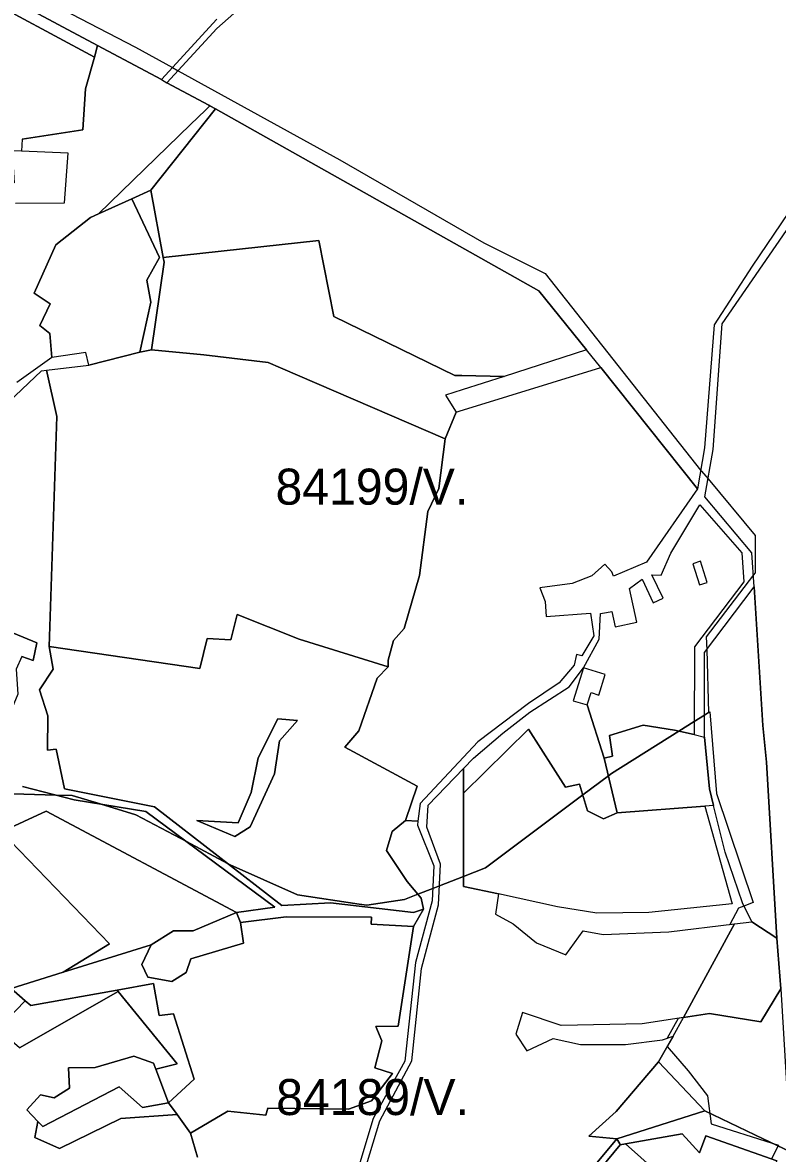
# Model space of a CAD drawing. Extents: x -477304 to -465429, y -1159113 to -1149210.
# Drawn here: x -474880.8 to -474566.3, y -1157226 to -1156755 of the extents above; entities that cross this region are included whole.
import ezdxf

# ---------------------------------------------------------------- set-up
doc = ezdxf.new("R2010")
doc.units = 0
for name, color, linetype in [('BPEJ_s', 7, 'Continuous'), ('PUPFL_s', 7, 'Continuous'), ('sad_s', 7, 'Continuous'), ('trav_porost_s', 7, 'Continuous'), ('zahrada_s', 7, 'Continuous')]:
    doc.layers.add(name, color=color, linetype=linetype)

msp = doc.modelspace()

# ---------------------------------------------------------------- linework, layer by layer
at = {"layer": 'BPEJ_s'}
for points in [[(-474910.48, -1156725.34), (-474833.78, -1156765.24), (-474818.36, -1156773.73), (-474815.98, -1156775.04), (-474748.53, -1156812.18), (-474688.56, -1156846.68), (-474662.99, -1156859.58), (-474598.28, -1156941.38), (-474597.89, -1156941.87), (-474595.22, -1156945.08), (-474575.63, -1156968.65), (-474575.63, -1156984.14), (-474576.28, -1156985), (-474595.92, -1157010.92), (-474595.77, -1157016.21), (-474595.07, -1157042.42), (-474596.66, -1157043.42), (-474600.95, -1157046.11), (-474607.31, -1157050.1), (-474635.4, -1157067.73), (-474636.7, -1157068.7), (-474647.39, -1157076.7), (-474666.82, -1157091.23), (-474687.96, -1157107.04), (-474697.12, -1157110.64), (-474707.06, -1157114.55), (-474709.92, -1157115.67), (-474716.07, -1157118.09), (-474721.66, -1157120.28), (-474737.3, -1157122.69), (-474740.55, -1157122.19), (-474766.19, -1157118.28), (-474794.27, -1157105.84), (-474795.36, -1157105.26), (-474812.52, -1157096.15), (-474833.58, -1157084.98), (-474848.45, -1157080.47), (-474860.06, -1157076.96), (-474866.9, -1157076.77), (-474898.2, -1157075.9)], [(-474910.48, -1156725.34), (-474833.78, -1156765.24), (-474818.36, -1156773.73), (-474815.98, -1156775.04), (-474748.53, -1156812.18), (-474688.56, -1156846.68), (-474662.99, -1156859.58), (-474598.28, -1156941.38), (-474597.89, -1156941.87), (-474595.22, -1156945.08), (-474575.63, -1156968.65), (-474575.63, -1156984.14), (-474576.28, -1156985), (-474595.92, -1157010.92), (-474595.77, -1157016.21), (-474595.07, -1157042.42), (-474594.48, -1157042.05), (-474591.67, -1157076.15), (-474576.43, -1157121.49), (-474580.25, -1157123.01), (-474582.45, -1157123.89)], [(-474898.2, -1157075.9), (-474866.9, -1157076.77), (-474860.06, -1157076.96), (-474848.45, -1157080.47), (-474833.58, -1157084.98), (-474812.52, -1157096.15), (-474795.36, -1157105.26), (-474794.27, -1157105.84), (-474766.19, -1157118.28), (-474740.55, -1157122.19), (-474737.3, -1157122.69), (-474721.66, -1157120.28), (-474716.07, -1157118.09), (-474709.92, -1157115.67), (-474707.06, -1157114.55), (-474697.12, -1157110.64), (-474687.96, -1157107.04), (-474666.82, -1157091.23), (-474647.39, -1157076.7), (-474636.7, -1157068.7), (-474635.4, -1157067.73), (-474607.31, -1157050.1), (-474600.95, -1157046.11), (-474596.66, -1157043.42), (-474595.07, -1157042.42), (-474594.48, -1157042.05), (-474591.67, -1157076.15), (-474576.43, -1157121.49), (-474580.25, -1157123.01), (-474582.45, -1157123.89), (-474586.17, -1157130.66), (-474584.16, -1157130.41), (-474605.49, -1157169.45), (-474607.69, -1157169.78), (-474612.24, -1157178.05), (-474609.75, -1157177.25), (-474612.17, -1157181.44), (-474603.51, -1157191.69), (-474595.49, -1157202.12), (-474593.88, -1157213.76), (-474568.54, -1157221.72), (-474565.8, -1157222.58)], [(-474582.45, -1157123.89), (-474586.17, -1157130.66), (-474584.16, -1157130.41), (-474605.49, -1157169.45), (-474607.69, -1157169.78), (-474612.24, -1157178.05), (-474609.75, -1157177.25), (-474612.17, -1157181.44), (-474603.51, -1157191.69), (-474595.49, -1157202.12), (-474593.88, -1157213.76), (-474568.54, -1157221.72), (-474565.8, -1157222.58), (-474565.99, -1157222.94), (-474568.82, -1157228.32)], [(-474565.99, -1157222.94), (-474568.82, -1157228.32)]]:
    msp.add_lwpolyline(points, dxfattribs=at)
at = {"layer": 'PUPFL_s'}
for points in [[(-475050.35, -1156724.49), (-474996.9, -1156722.67), (-474961.41, -1156717.1), (-474960.45, -1156713.18), (-474943.01, -1156716.72), (-474943.36, -1156718.88), (-474915.25, -1156729.45), (-474849.5, -1156764.55), (-474850.84, -1156769.41), (-474917.11, -1156733.69), (-474943.69, -1156724.45), (-474962.53, -1156722.23), (-474995.47, -1156727.45), (-475052.09, -1156729.69)], [(-474802.7, -1156789.7), (-474800.43, -1156790.91), (-474827.36, -1156824.84), (-474835.24, -1156828.37), (-474849.11, -1156834.6), (-474810.78, -1156797.51), (-474804.6, -1156791.54)], [(-474822.17, -1156852.91), (-474827.36, -1156824.84), (-474800.43, -1156790.91), (-474696.54, -1156849.32), (-474665.65, -1156866.69), (-474645.81, -1156891.37), (-474680.15, -1156902.39), (-474697.83, -1156902.04), (-474700.63, -1156901.99), (-474751.16, -1156877.41), (-474757.34, -1156845.8)], [(-474572.44, -1157047.84), (-474570.88, -1157063.12), (-474566.57, -1157136.41), (-474577.01, -1157129.52), (-474580.91, -1157121.68), (-474588.03, -1157100.57), (-474592.92, -1157081.06), (-474594.63, -1157074.21), (-474596.67, -1157052.59), (-474596.64, -1157017.35), (-474575.93, -1156990.04)], [(-474899.13, -1157070.68), (-474916.01, -1157075.74), (-474938.95, -1157077.02), (-474954.17, -1157078.25), (-474987.5, -1157074.55), (-475015.54, -1157060.67), (-474955.56, -1157054.06), (-474895.66, -1157047.4), (-474884.52, -1157009.38), (-474874.79, -1157013.4), (-474876.41, -1157020.73), (-474881.13, -1157019.11), (-474883.41, -1157024.26), (-474882.74, -1157034.73), (-474885.83, -1157042.11), (-474889.45, -1157047.94), (-474898.18, -1157051.61), (-474901.76, -1157056.2), (-474896.84, -1157066.23)], [(-474870.93, -1157083.43), (-474791.58, -1157125.7), (-474809.64, -1157133.34), (-474817.86, -1157133.29), (-474827.16, -1157139.1), (-474863.81, -1157150.57), (-474844.56, -1157138.8), (-474889.52, -1157092.08)], [(-474885.46, -1157157.34), (-474863.81, -1157150.57), (-474827.16, -1157139.1), (-474831.12, -1157147.34), (-474828.52, -1157152.62), (-474818.58, -1157154.46), (-474812.65, -1157150.67), (-474810.67, -1157145.03), (-474788.67, -1157138.53), (-474790.04, -1157129.85), (-474770.97, -1157127.53), (-474735.38, -1157127.68), (-474735.49, -1157130.57), (-474717.93, -1157131.51), (-474724.3, -1157173.08), (-474733.65, -1157173.24), (-474731.13, -1157179.21), (-474733.98, -1157190.4), (-474726.72, -1157192.71), (-474735.37, -1157204.16), (-474744.95, -1157207.61), (-474778.63, -1157207.26), (-474779.36, -1157210.08), (-474795.27, -1157208.41), (-474810.86, -1157217.55), (-474816.41, -1157209.79), (-474819.97, -1157204.97), (-474809.26, -1157195.07), (-474817.86, -1157167.91), (-474823.93, -1157168.6), (-474826.26, -1157155.32), (-474841.42, -1157158.09), (-474877.38, -1157164.49), (-474879.64, -1157162.52)], [(-474790.04, -1157129.85), (-474788.67, -1157138.53), (-474810.67, -1157145.03), (-474812.65, -1157150.67), (-474818.58, -1157154.46), (-474828.52, -1157152.62), (-474831.12, -1157147.34), (-474827.16, -1157139.1), (-474817.86, -1157133.29), (-474809.64, -1157133.34), (-474791.58, -1157125.7)], [(-474584.16, -1157130.41), (-474577.01, -1157129.52), (-474566.57, -1157136.41), (-474564.87, -1157157.45), (-474573.26, -1157171.3), (-474594.56, -1157167.78), (-474605.49, -1157169.45)], [(-474826.26, -1157155.32), (-474823.93, -1157168.6), (-474817.86, -1157167.91), (-474809.26, -1157195.07), (-474819.97, -1157204.97), (-474825.25, -1157190.92), (-474816.38, -1157188.78), (-474840.97, -1157158.64), (-474841.42, -1157158.09)], [(-474560.83, -1157225.42), (-474572.19, -1157219.97), (-474596.58, -1157208.26), (-474615.85, -1157187.83), (-474609.75, -1157177.25), (-474605.49, -1157169.45), (-474594.56, -1157167.78), (-474573.26, -1157171.3), (-474564.87, -1157157.45), (-474561, -1157222.59)], [(-474841.42, -1157158.09), (-474840.97, -1157158.64), (-474882.08, -1157182.04), (-474891.25, -1157174.3), (-474879.64, -1157162.52), (-474877.38, -1157164.49)], [(-474840.56, -1157198.28), (-474872.33, -1157214.78), (-474874.37, -1157212.68), (-474878.97, -1157207.94), (-474873.24, -1157201.61), (-474867.67, -1157202.84), (-474861.27, -1157198.93), (-474861.69, -1157190.35), (-474850.56, -1157190.29), (-474834.35, -1157185.49), (-474826.18, -1157188.45), (-474825.25, -1157190.92), (-474819.97, -1157204.97), (-474830.81, -1157206.94)], [(-474596.58, -1157208.26), (-474633.21, -1157219.92), (-474644.9, -1157218.82), (-474633.44, -1157208.55), (-474615.85, -1157187.83)], [(-474819.97, -1157204.97), (-474816.41, -1157209.79), (-474839.83, -1157211.52), (-474865.42, -1157223.93), (-474875.71, -1157219.47), (-474874.37, -1157212.68), (-474872.33, -1157214.78), (-474840.56, -1157198.28), (-474830.81, -1157206.94)], [(-474585.32, -1157258.29), (-474592.58, -1157249.28), (-474610.48, -1157239.07), (-474629.62, -1157222.07), (-474606.02, -1157217.85), (-474598.76, -1157225.82), (-474596.12, -1157218.7), (-474566.5, -1157229.14), (-474577.17, -1157250.19)]]:
    msp.add_lwpolyline(points, close=True, dxfattribs=at)
for points in [[(-474799.8, -1156753.54), (-474822.94, -1156778.71), (-474849.5, -1156764.55), (-474915.25, -1156729.45)], [(-474561.74, -1156834.07), (-474576.86, -1156856.4), (-474592.59, -1156880.96), (-474596.64, -1156932.07), (-474599.66, -1156949.17), (-474639.91, -1156898.7), (-474645.81, -1156891.37), (-474665.65, -1156866.69), (-474696.54, -1156849.32), (-474800.43, -1156790.91), (-474802.7, -1156789.7), (-474803.2, -1156789.43), (-474820.67, -1156780.13), (-474799.84, -1156757.52), (-474773.73, -1156734.29)], [(-474564.87, -1157157.45), (-474566.57, -1157136.41), (-474570.88, -1157063.12), (-474572.44, -1157047.84), (-474575.93, -1156990.04), (-474576.91, -1156975.84), (-474596.49, -1156952.51), (-474593.11, -1156932.76), (-474589.27, -1156880.49), (-474559.69, -1156837.53)], [(-474566.5, -1157229.14), (-474596.12, -1157218.7), (-474598.76, -1157225.82), (-474606.02, -1157217.85), (-474629.62, -1157222.07), (-474631.77, -1157222.45), (-474632, -1157222.05), (-474633.21, -1157219.92), (-474596.58, -1157208.26), (-474572.19, -1157219.97), (-474560.83, -1157225.42), (-474520.06, -1157230.66)], [(-474641.34, -1157229.79), (-474633.21, -1157219.92), (-474632, -1157222.05), (-474631.77, -1157222.45), (-474654.35, -1157249.7)]]:
    msp.add_lwpolyline(points, dxfattribs=at)
at = {"layer": 'sad_s'}
for points in [[(-474622.63, -1156986.84), (-474618.06, -1156996.69), (-474613.96, -1156994.71), (-474618.65, -1156984.99), (-474614.68, -1156985.24), (-474610.7, -1156975.97), (-474598.57, -1156955.93), (-474581.13, -1156975.81), (-474580.25, -1156988.01), (-474600.88, -1157015.06), (-474600.97, -1157051.58), (-474609.13, -1157049.68), (-474622.22, -1157047.6), (-474636.27, -1157051.92), (-474634.94, -1157060.53), (-474638.42, -1157061.35), (-474645.54, -1157039.25), (-474643.96, -1157034.09), (-474640.66, -1157035.1), (-474638.02, -1157026.51), (-474647.14, -1157023.71), (-474640.58, -1157011.8), (-474639.94, -1157001.19), (-474637.52, -1157000.73), (-474635.26, -1157000.24), (-474633.94, -1157006.65), (-474624.91, -1157004.71), (-474627.92, -1156990.68)], [(-474598.8, -1156989.18), (-474595.58, -1156988.19), (-474598.28, -1156979.4), (-474601.5, -1156980.39)]]:
    msp.add_lwpolyline(points, close=True, dxfattribs=at)
at = {"layer": 'trav_porost_s'}
for points in [[(-474917.11, -1156733.69), (-474850.84, -1156769.41), (-474854.5, -1156782.61), (-474855.65, -1156799.69), (-474880.95, -1156803.52), (-474881.2, -1156808.54), (-474885.06, -1156808.36), (-474884.2, -1156821.7), (-474890.84, -1156821.58), (-474898.09, -1156823.96), (-474910, -1156822.29), (-474919.21, -1156823.96), (-474937.87, -1156822.95), (-474956.33, -1156815.29), (-474954.66, -1156799.69), (-474957.43, -1156799.06), (-474956.8, -1156783.48), (-474969.9, -1156783.16), (-474979.46, -1156770.59), (-475008.23, -1156766.57), (-475008.3, -1156757.48), (-475065.69, -1156758.54), (-475057.96, -1156746.55)], [(-474880.95, -1156803.52), (-474855.65, -1156799.69), (-474854.5, -1156782.61), (-474850.84, -1156769.41), (-474849.5, -1156764.55), (-474822.94, -1156778.71), (-474820.67, -1156780.13), (-474803.2, -1156789.43), (-474802.7, -1156789.7), (-474804.6, -1156791.54), (-474810.78, -1156797.51), (-474849.11, -1156834.6), (-474852.51, -1156836.13), (-474866.92, -1156847.55), (-474875.91, -1156867.71), (-474869.28, -1156872.11), (-474873.55, -1156881.11), (-474869.47, -1156884.55), (-474868.62, -1156894.47), (-474883.15, -1156904.87)], [(-474883.65, -1156830.25), (-474863.32, -1156830.02), (-474861.74, -1156809.45), (-474881.2, -1156808.54)], [(-474900.21, -1156925.95), (-474872.85, -1156900.05), (-474870.76, -1156899.79), (-474866.46, -1156919.14), (-474869.63, -1157014.82), (-474867.97, -1157024.34), (-474873.65, -1157032.91), (-474870.2, -1157043.77), (-474870.4, -1157058.12), (-474866.82, -1157057.71), (-474863.3, -1157074.24), (-474825.8, -1157081.72), (-474772.76, -1157122.74), (-474752.48, -1157121.69), (-474717.92, -1157125.65), (-474713.79, -1157124.35), (-474717.93, -1157131.51), (-474735.49, -1157130.57), (-474735.38, -1157127.68), (-474770.97, -1157127.53), (-474790.04, -1157129.85), (-474791.58, -1157125.7), (-474775.67, -1157123.44), (-474829.48, -1157083.6), (-474859.22, -1157078.7), (-474880.78, -1157073.27)], [(-474881.13, -1157019.11), (-474876.41, -1157020.73), (-474874.79, -1157013.4), (-474884.52, -1157009.38)], [(-474744.45, -1157253.74), (-474731.98, -1157212.54), (-474718.64, -1157187.47), (-474714.57, -1157149.07), (-474707.46, -1157122.5), (-474706.6, -1157105.5), (-474712.3, -1157090.12), (-474711.77, -1157081.02), (-474697.14, -1157065.72), (-474697.14, -1157075.96), (-474697.12, -1157114.79), (-474682.5, -1157117.96), (-474683.74, -1157126.33), (-474676.33, -1157130.37), (-474666.69, -1157138.27), (-474654.51, -1157143.3), (-474647.29, -1157133.3), (-474638.93, -1157134.9), (-474611.52, -1157133.81), (-474584.16, -1157130.41), (-474605.49, -1157169.45), (-474622.58, -1157172.06), (-474656.34, -1157172.79), (-474672.48, -1157167.35), (-474675.21, -1157176.43), (-474670.72, -1157183.31), (-474659.7, -1157178.19), (-474648.37, -1157180.72), (-474629.54, -1157180.69), (-474614.24, -1157178.7), (-474609.75, -1157177.25), (-474615.85, -1157187.83), (-474633.44, -1157208.55), (-474644.9, -1157218.82), (-474633.21, -1157219.92), (-474641.34, -1157229.79)], [(-474880.78, -1157073.27), (-474859.22, -1157078.7), (-474829.48, -1157083.6), (-474775.67, -1157123.44), (-474791.58, -1157125.7), (-474870.93, -1157083.43), (-474889.52, -1157092.08), (-474844.56, -1157138.8), (-474863.81, -1157150.57), (-474885.46, -1157157.34), (-474879.64, -1157162.52), (-474891.25, -1157174.3)], [(-474807.85, -1157227.61), (-474810.86, -1157217.55), (-474795.27, -1157208.41), (-474779.36, -1157210.08), (-474778.63, -1157207.26), (-474744.95, -1157207.61), (-474735.37, -1157204.16), (-474726.72, -1157192.71), (-474733.98, -1157190.4), (-474731.13, -1157179.21), (-474733.65, -1157173.24), (-474724.3, -1157173.08), (-474717.93, -1157131.51), (-474713.79, -1157124.35), (-474714.76, -1157119.68), (-474720.48, -1157112.75), (-474729.18, -1157099.93), (-474726.76, -1157091.95), (-474721.28, -1157087.35), (-474716.08, -1157087.65), (-474716.28, -1157089.36), (-474709.5, -1157106.25), (-474710.15, -1157120.87), (-474717.1, -1157146.51), (-474721.55, -1157187.56), (-474734.77, -1157211.44), (-474746.21, -1157249.78)], [(-474882.08, -1157182.04), (-474840.97, -1157158.64), (-474816.38, -1157188.78), (-474825.25, -1157190.92), (-474826.18, -1157188.45), (-474834.35, -1157185.49), (-474850.56, -1157190.29), (-474861.69, -1157190.35), (-474861.27, -1157198.93), (-474867.67, -1157202.84), (-474873.24, -1157201.61), (-474878.97, -1157207.94), (-474874.37, -1157212.68), (-474875.71, -1157219.47), (-474865.42, -1157223.93), (-474839.83, -1157211.52), (-474816.41, -1157209.79), (-474810.86, -1157217.55), (-474807.85, -1157227.61)]]:
    msp.add_lwpolyline(points, dxfattribs=at)
for points in [[(-474835.24, -1156828.37), (-474827.36, -1156824.84), (-474822.17, -1156852.91), (-474821.83, -1156854.75), (-474826.99, -1156891.24), (-474831.94, -1156892.27), (-474827.29, -1156871.48), (-474828.98, -1156862.34), (-474823.7, -1156852.78)], [(-474849.11, -1156834.6), (-474835.24, -1156828.37), (-474823.7, -1156852.78), (-474828.98, -1156862.34), (-474827.29, -1156871.48), (-474831.94, -1156892.27), (-474853.14, -1156897.63), (-474854.42, -1156892.4), (-474868.62, -1156894.47), (-474869.47, -1156884.55), (-474873.55, -1156881.11), (-474869.28, -1156872.11), (-474875.91, -1156867.71), (-474866.92, -1156847.55), (-474852.51, -1156836.13)], [(-474751.16, -1156877.41), (-474700.63, -1156901.99), (-474697.83, -1156902.04), (-474680.15, -1156902.39), (-474697.57, -1156907.98), (-474704.57, -1156910.22), (-474700.19, -1156917.31), (-474704.76, -1156928.45), (-474773.25, -1156898.86), (-474778.46, -1156896.61), (-474805.27, -1156893.34), (-474826.99, -1156891.24), (-474821.83, -1156854.75), (-474822.17, -1156852.91), (-474757.34, -1156845.8)], [(-474773.25, -1156898.86), (-474704.76, -1156928.45), (-474707.42, -1156949.11), (-474711.92, -1156958.64), (-474715.41, -1156985.25), (-474721.76, -1157007.37), (-474726.25, -1157012.44), (-474728.5, -1157020.58), (-474728.44, -1157023.36), (-474765.56, -1157011.88), (-474791.3, -1157001.58), (-474794.01, -1157012.04), (-474803.83, -1157011.5), (-474806.92, -1157024.07), (-474869.63, -1157014.82), (-474866.46, -1156919.14), (-474870.76, -1156899.79), (-474853.14, -1156897.63), (-474831.94, -1156892.27), (-474826.99, -1156891.24), (-474805.27, -1156893.34), (-474778.46, -1156896.61)], [(-474644.21, -1157000.95), (-474642.85, -1157010.42), (-474647.78, -1157018.79), (-474650.04, -1157018.25), (-474651, -1157022.63), (-474657.28, -1157030.08), (-474669.97, -1157038.63), (-474691.14, -1157054.63), (-474715.2, -1157080.22), (-474716.08, -1157087.65), (-474721.28, -1157087.35), (-474716.44, -1157073.01), (-474746.55, -1157056.83), (-474740.62, -1157050.03), (-474733.04, -1157028.11), (-474728.44, -1157023.36), (-474728.5, -1157020.58), (-474726.25, -1157012.44), (-474721.76, -1157007.37), (-474715.41, -1156985.25), (-474711.92, -1156958.64), (-474707.42, -1156949.11), (-474704.76, -1156928.45), (-474700.19, -1156917.31), (-474698.85, -1156916.89), (-474639.91, -1156898.7), (-474599.66, -1156949.17), (-474620.91, -1156979.79), (-474634.58, -1156985.56), (-474635.33, -1156983.82), (-474638.18, -1156980.61), (-474643.59, -1156985.41), (-474651.76, -1156988.61), (-474665.23, -1156990.43), (-474663.11, -1156996.19), (-474662.62, -1157002.38)], [(-474714.76, -1157119.68), (-474713.79, -1157124.35), (-474717.92, -1157125.65), (-474752.48, -1157121.69), (-474772.76, -1157122.74), (-474825.8, -1157081.72), (-474863.3, -1157074.24), (-474866.82, -1157057.71), (-474870.4, -1157058.12), (-474870.2, -1157043.77), (-474873.65, -1157032.91), (-474867.97, -1157024.34), (-474869.63, -1157014.82), (-474806.92, -1157024.07), (-474803.83, -1157011.5), (-474794.01, -1157012.04), (-474791.3, -1157001.58), (-474765.56, -1157011.88), (-474728.44, -1157023.36), (-474733.04, -1157028.11), (-474740.62, -1157050.03), (-474746.55, -1157056.83), (-474716.44, -1157073.01), (-474721.28, -1157087.35), (-474726.76, -1157091.95), (-474729.18, -1157099.93), (-474720.48, -1157112.75)], [(-474680.71, -1157050.93), (-474669.39, -1157042.24), (-474653.09, -1157031.68), (-474647.14, -1157023.71), (-474651.36, -1157037.47), (-474645.54, -1157039.25), (-474638.42, -1157061.35), (-474633.1, -1157084.14), (-474638.77, -1157086.61), (-474645.43, -1157083.35), (-474648.71, -1157072.24), (-474654.58, -1157073.47), (-474669.94, -1157049.33), (-474697.14, -1157075.96), (-474697.14, -1157065.72), (-474692.97, -1157061.36)], [(-474785.9, -1157090.03), (-474792.38, -1157094.06), (-474808.19, -1157087.4), (-474790.93, -1157088.38), (-474785.53, -1157075.75), (-474782.57, -1157061.26), (-474774.47, -1157045.03), (-474766.17, -1157045.68), (-474773.68, -1157054.13), (-474775.83, -1157067.95)], [(-474785.9, -1157090.03), (-474775.83, -1157067.95), (-474773.68, -1157054.13), (-474766.17, -1157045.68), (-474774.47, -1157045.03), (-474782.57, -1157061.26), (-474785.53, -1157075.75), (-474790.93, -1157088.38), (-474808.19, -1157087.4), (-474792.38, -1157094.06)], [(-474654.58, -1157073.47), (-474648.71, -1157072.24), (-474645.43, -1157083.35), (-474638.77, -1157086.61), (-474633.1, -1157084.14), (-474596.48, -1157081.33), (-474585.17, -1157122.12), (-474619.82, -1157125.74), (-474641.53, -1157125.93), (-474657.96, -1157123.35), (-474682.5, -1157117.96), (-474697.12, -1157114.79), (-474697.14, -1157075.96), (-474669.94, -1157049.33)], [(-474604.43, -1157274.23), (-474611.29, -1157273.73), (-474637.99, -1157260.32), (-474654.35, -1157249.7), (-474631.77, -1157222.45), (-474629.62, -1157222.07), (-474610.48, -1157239.07), (-474592.58, -1157249.28), (-474585.32, -1157258.29), (-474591.99, -1157264.92)]]:
    msp.add_lwpolyline(points, close=True, dxfattribs=at)
at = {"layer": 'zahrada_s'}
msp.add_lwpolyline([(-474600.97, -1157051.58), (-474596.67, -1157052.59), (-474594.63, -1157074.21), (-474592.92, -1157081.06), (-474596.48, -1157081.33), (-474633.1, -1157084.14), (-474638.42, -1157061.35), (-474634.94, -1157060.53), (-474636.27, -1157051.92), (-474622.22, -1157047.6), (-474609.13, -1157049.68)], close=True, dxfattribs=at)

# ---------------------------------------------------------------- texts
at = {"layer": 'BPEJ_s'}
for s, p in [('84199/V.', (-474775.39, -1156955.8)), ('84189/V.', (-474775.12, -1157210.06))]:
    msp.add_text(s, height=15, dxfattribs=at).set_placement(p)

doc.saveas('drawing.dxf')
